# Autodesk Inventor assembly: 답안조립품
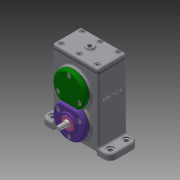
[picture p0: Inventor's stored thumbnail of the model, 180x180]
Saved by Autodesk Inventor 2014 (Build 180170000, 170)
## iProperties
Created: 2020-05
Part Number: 답안조립품
Document SubType Name: Assembly
Designer: kh
Mass: 1076.75 g
Surface Area: 1575.48 cm^2
Volume: 384.079 cm^3
Density: 2.80345 g/cm^3
Author: kh
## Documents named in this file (24)
- C:\Users\kh\Desktop\600506V1030\답안조립품.iam
- C:\Users\kh\Desktop\600506V1030\본체.ipt
- C:\Users\kh\Desktop\600506V1030\개스킷 A.ipt
- C:\Users\kh\Desktop\600506V1030\개스킷 B.ipt
- C:\Users\kh\Desktop\600506V1030\개스킷 C.ipt
- C:\Users\kh\Desktop\600506V1030\베어링 6001.ipt
- 베어링 6001.ipt
- C:\Users\kh\Desktop\600506V1030\베어링 6002.ipt
- 베어링 6002.ipt
- C:\Users\kh\Desktop\600506V1030\볼트 M4.ipt
- C:\Users\kh\Desktop\600506V1030\스퍼기어 A.ipt
- C:\Users\kh\Desktop\600506V1030\스퍼기어 B.ipt
- C:\Users\kh\Desktop\600506V1030\오일 실 10 20 7.ipt
- C:\Users\kh\Desktop\600506V1030\오일 실 12 22 7.ipt
- C:\Users\kh\Desktop\600506V1030\축 A.ipt
- C:\Users\kh\Desktop\600506V1030\축 B.ipt
- C:\Users\kh\Desktop\600506V1030\칼라.ipt
- C:\Users\kh\Desktop\600506V1030\커버 A.ipt
- C:\Users\kh\Desktop\600506V1030\커버 B.ipt
- C:\Users\kh\Desktop\600506V1030\커버 C.ipt
- C:\Users\kh\Desktop\600506V1030\커버 D.ipt
- C:\Users\kh\Desktop\600506V1030\커버 E.ipt
- C:\Users\kh\Desktop\600506V1030\키 4 x 4 x 12.ipt
- C:\Users\kh\Desktop\600506V1030\키 5 x 5 x 12.ipt
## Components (5 placed, 3 different names)
1. 개스킷 C:1 — Mate:1, Mate:2, Mate:3, Mate:4, Mate:5, Mate:6
2. 개스킷 A:1 — Mate:10, Mate:11, Mate:12, Mate:13
3. 개스킷 B:1 — Mate:7, Mate:8, Mate:9, Mate:16
4. 개스킷 B:2 — Mate:22, Mate:23, Mate:24, Mate:25
5. 개스킷 B:3 — Mate:31, Mate:32, Mate:33, Mate:34
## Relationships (22: Mate 22)
- Mate:1: 개스킷 C:1
- Mate:2: 개스킷 C:1
- Mate:3: 개스킷 C:1
- Mate:4: 개스킷 C:1
- Mate:5: 개스킷 C:1
- Mate:6: 개스킷 C:1
- Mate:7: 개스킷 B:1
- Mate:8: 개스킷 B:1
- Mate:9: 개스킷 B:1
- Mate:10: 개스킷 A:1
- Mate:11: 개스킷 A:1
- Mate:12: 개스킷 A:1
- Mate:13: 개스킷 A:1
- Mate:16: 개스킷 B:1
- Mate:22: 개스킷 B:2
- Mate:23: 개스킷 B:2
- Mate:24: 개스킷 B:2
- Mate:25: 개스킷 B:2
- Mate:31: 개스킷 B:3
- Mate:32: 개스킷 B:3
- Mate:33: 개스킷 B:3
- Mate:34: 개스킷 B:3
